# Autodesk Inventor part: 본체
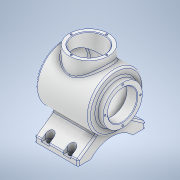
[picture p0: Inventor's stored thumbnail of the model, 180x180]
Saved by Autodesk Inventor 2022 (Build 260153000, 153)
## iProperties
Created: 2023-04
Part Number: 본체
Material: 알루미늄 6061
Document SubType Name: Modeling
Designer: Admin
Mass: 1269.02 g
Surface Area: 1058.92 cm^2
Volume: 470.009 cm^3
Density: 2.7 g/cm^3
Appearance: 알루미늄 - 평지
Author: Admin
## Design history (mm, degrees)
sketch "스케치1"
  geometry: L1 (0, 62)-(10, 62); L2 (10, 62)-(48.324, 7.268); L3 (48.324, 7.268)-(48.324, -7.268); L4 (48.324, -7.268)-(10, -62); L5 (10, -62)-(0, -62); L6 (-51.779, 0)-(65.008, 0) reference; L7 (0, -86.8)-(0, 86.8) reference; L8 (17, 38.5)-(17, -38.5); L9 (0, 62)-(0, 38.5); L10 (0, -38.5)-(0, -62); A1 r 52.096 centre (-35.096, 0) between (0, -38.5) and (0, 38.5); 1 further point
  constraints: 16 end point, 2 point on circle, 2 point on line, 2 vertical, 1 centre point, 1 horizontal, 1 parallel, 1 perpendicular, 1 tangent, 2 other
  dimensions: "d0" = 124 distance between parallel lines of L5 L1; "d2" = 10 distance of L1.start L1.end; "d3" = 10 distance of L4.end L5.end; "d4" = 55 deg angle of L5 L4; "d5" = 55 deg angle of L1 L2; "d6" = 77 distance of L10.start L9.end; "d7" = 17 distance between parallel lines of L10 L8; "d9" = 23.5 distance of L1.start L9.end
extrude "돌출1" new body sketch "스케치1" stored distance "d10" = 80; taper "d11" = 0 deg
sketch "스케치2"
  geometry: L1 (137.042, 77)-(-124.448, 77); L2 (-40, 0)-(40, 0) reference; L3 (0, -15.4)-(0, 92.4) reference; L4 (-48.336, 77)-(48, 77); L5 (48, 77)-(48, 127); L6 (48, 127)-(-48.336, 127); L7 (-48.336, 127)-(-48.336, 77); L8 (-60, 77)-(-60, 148.1); L9 (48, 77)-(60, 77); L10 (60, 77)-(60, 113); L11 (60, 113)-(48, 113); L12 (48, 113)-(48, 77); L13 (40, 48.324)-(40, 10) reference; L14 (60, 77)-(-60, 77); A1 r 113 centre (53, 77) between (-48.336, 127) and (-60, 77); 3 further points
  constraints: 22 end point, 4 parallel, 3 horizontal, 3 point on line, 2 perpendicular, 2 point on circle, 1 centre point, 1 collinear, 1 tangent, 1 vertical
  dimensions: "d13" = 77 distance from line of point (0, 0) L1; "d15" = 100 diameter of L6 L1; "d16" = 20 distance between parallel lines of L13 L10; "d17" = 120 distance between parallel lines of L8 L10; "d18" = 108 distance between parallel lines of L8 L12; "d19" = 72 diameter of L11 L1; "d20" = 226 diameter of A1
revolve "회전1" sketch "스케치2" stored, may be unused: angle "d21" = 90 deg
node "작업 평면1"
sketch "스케치3"
  geometry: L1 (-60, 36)-(-60, -36) reference; C1 r 36 at (2, 0); 1 further point
  constraints: 1 centre point, 1 coincident
  dimensions: "d23" = 72 diameter of C1; "d96" = 62 distance from line of L1 point (2, 0)
extrude "돌출2" join sketch "스케치3" distance "d24" = 65; taper "d25" = 0 deg
sketch "스케치7"
  geometry: L1 (-26.694, 34.722)-(-62, 10) reference; L2 (-62, 10)-(-62, 0) reference; L3 (-62, 0)-(-38.5, 0) reference; L4 (38.5, 0)-(62, 0) reference; L5 (62, 0)-(62, 10) reference; L6 (62, 10)-(26.694, 34.722) reference; A1 r 50 centre (0, 77) between (-26.694, 34.722) and (26.694, 34.722) reference; A2 r 52.096 centre (0, -35.096) between (38.5, 0) and (-38.5, 0) reference; 1 further point
  node "투영된 루프2"
extrude "돌출3" cut sketch "스케치7" extent not by distance; stored distance "d29" = 0; taper "d30" = 0 deg
feature "쉘2" dims "d31" = 7
extrude "돌출4" join sketch "스케치7" distance "d32" = 80; taper "d33" = 0 deg
node "작업 평면2"
sketch "스케치9" dims "d44" = 10
  geometry: L1 (40, -62)-(-40, -62) reference; L2 (40, 62)-(-40, 62) reference; L3 (27, -54)-(27, -62); L4 (13, -54)-(13, -62); L5 (40, -62)-(40, -38.5) reference; L6 (-13, -54)-(-13, -62); L7 (-27, -54)-(-27, -62); L8 (84, 0)-(-84, 0) reference; L9 (13, 54)-(13, 62); L10 (27, 54)-(27, 62); L11 (-13, 54)-(-13, 62); L12 (-27, 54)-(-27, 62); L13 (27, 62)-(13, 62); L14 (-13, 62)-(-27, 62); L15 (27, -62)-(13, -62); L16 (-13, -62)-(-27, -62); A1 r 7 centre (20, -54) between (27, -54) and (13, -54); A2 r 7 centre (-20, -54) between (-13, -54) and (-27, -54); A3 r 7 centre (20, 54) between (27, 54) and (13, 54); A4 r 7 centre (-20, 54) between (-13, 54) and (-27, 54); 7 further points
  constraints: 24 end point, 10 symmetric about line, 8 point on circle, 4 centre point, 3 collinear, 2 perpendicular, 2 point on line, 1 coincident, 1 horizontal, 10 other
  dimensions: "d35" = 20 distance from line of L5 A1.centre; "d36" = 14 distance between parallel lines of L4 L3; "d37" = 14 diameter of A1; "d38" = 8 distance from line of L1 A1.centre; "d41" = 40 distance of A1.centre A2.centre
extrude "돌출5" cut sketch "스케치9" distance "d46" = 30; taper "d47" = 0 deg
sketch "스케치10"
  geometry: L1 (13, -54)-(13, -62) reference; L2 (27, -62)-(13, -62) reference; L3 (27, -62)-(27, -54) reference; L4 (27, 54)-(27, 62) reference; L5 (13, 62)-(27, 62) reference; L6 (13, 62)-(13, 54) reference; A1 r 7 centre (-20, 54) between (-27, 54) and (-13, 54) reference; A2 r 7 centre (-20, -54) between (-13, -54) and (-27, -54) reference; A3 r 7 centre (20, -54) between (27, -54) and (13, -54) reference; A4 r 7 centre (20, 54) between (13, 54) and (27, 54) reference; 5 further points
  constraints: 4 coincident
hole "구멍1" sketch "스케치10" at (-20, -54), (20, -54), (-20, 54), (20, 54) diameter "d48" = 9; stored, may be unused: countersink angle "d52" = 90 deg, drill point angle "d54" = 118 deg; dims "d49" = 6, "d50" = 4, "d51" = 2, "d53" = 8
sketch "스케치11"
  geometry: L1 (0, -105.4)-(0, 93.4) reference; C1 r 36 at (0, 0) reference; 2 further points
  constraints: 1 point on line
  dimensions: "d55" = 32.5 distance of C1.centre point (0, 32.5)
hole "구멍2" sketch "스케치11" at (0, 32.5) diameter "d56" = 3.242; stored, may be unused: countersink angle "d60" = 90 deg, drill point angle "d62" = 118 deg; dims "d57" = 8, "d58" = 4, "d59" = 2, "d61" = 10
sketch "스케치16"
  geometry: C1 r 29 at (0, 0) reference; C2 r 27 at (0, 0); 1 further point
  constraints: 1 centre point, 1 coincident
  dimensions: "d69" = 54 diameter of C2
extrude "돌출7" join sketch "스케치16" distance "d70" = 19; taper "d71" = 0 deg
fillet "모깎기1" dims "d72" = 3
fillet "모깎기2" dims "d73" = 3
chamfer "모따기1" distance "d74" = 1; stored, may be unused: second distance "d75" = 2, angle "d76" = 45 deg
sketch "스케치24"
  geometry: L1 (-73, 107)-(-73, 35) reference; 2 further points
  constraints: 1 other
  dimensions: "d92" = 62 distance from line of L1 point (-11, 71); "d93" = 77 vertical distance of point (-13, -6) point (-11, 71)
feature "엠보싱1" sketch "스케치24" dims "d0" = 124, "d2" = 10, "d3" = 10, "d4" = 55 deg, "d5" = 55 deg, "d6" = 77, "d7" = 17, "d9" = 23.5, "d94" = 0.5, "d95" = 0
sketch "스케치25"
  geometry: L1 (0, -93.27)-(0, 97.614); L2 (62, -36)-(62, 36) reference; 2 further points
  constraints: 2 end point, 1 point on line, 1 vertical
  dimensions: "d97" = 62 distance between parallel lines of L2 L1; "d98" = 32.5 vertical distance of point (2, 0) point (0, -32.5)
hole "구멍4" sketch "스케치25" at (0, -32.5) diameter "d99" = 3.242; stored, may be unused: countersink angle "d103" = 90 deg, drill point angle "d105" = 118 deg; dims "d100" = 8, "d101" = 4, "d102" = 2, "d104" = 10
node "솔리드1"
pattern_circular "원형 패턴1" dims angle "d64" = 360 deg
pattern_circular "원형 패턴3" dims angle "d107" = 360 deg
node "투영된 루프3"
node "투영된 루프4"
feature "A9D066F2-1C7D-4E18-AEED-F7BC21143FA4" dims "d48" = 9, "d49" = 6, "d50" = 4, "d51" = 2, "d52" = 90 deg, "d53" = 8, "d54" = 118 deg
other parameters: "d22" = 77, "d34" = 6
